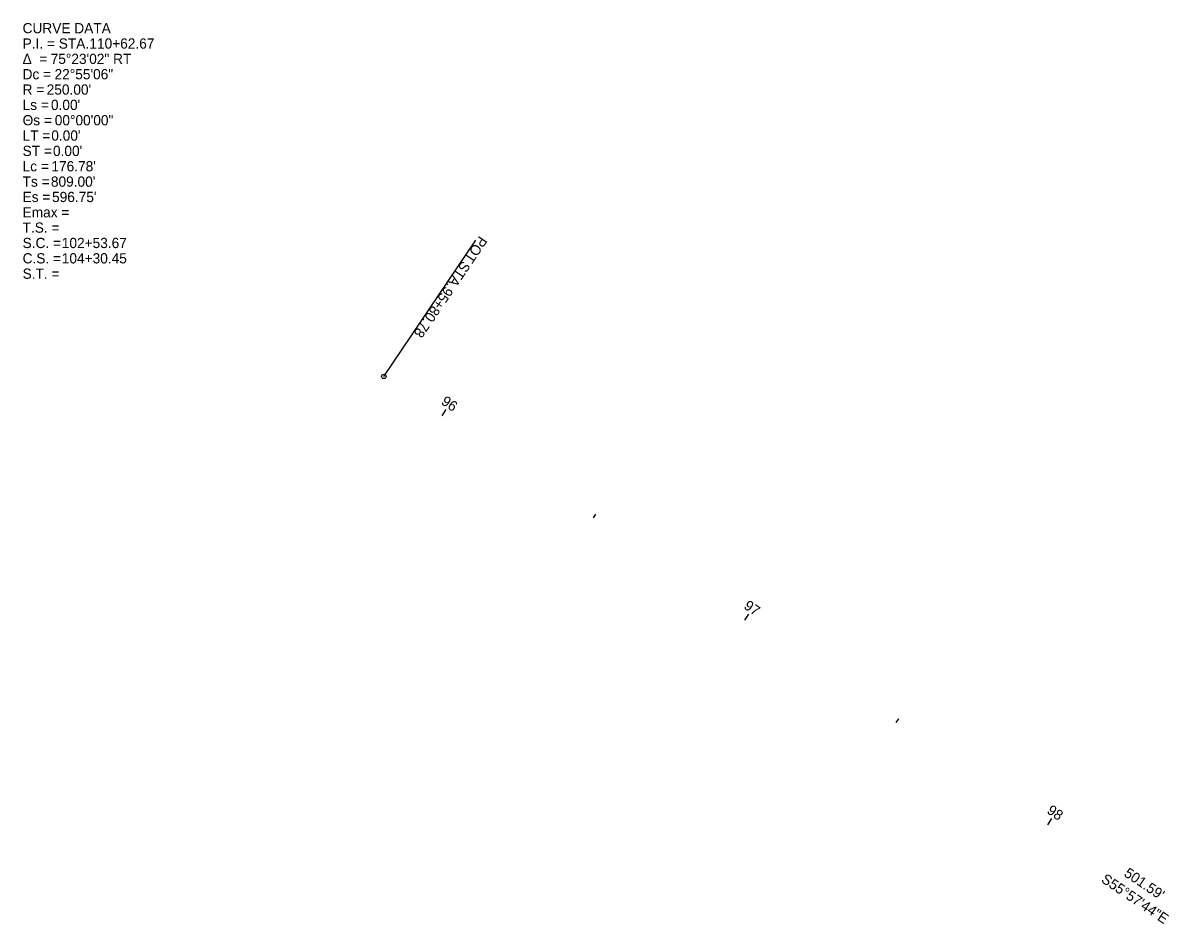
# Model space of a CAD drawing. Extents: x 1600023 to 1602131, y 285824 to 287284.
# Drawn here: x 1600258.1 to 1600571.8, y 287037.4 to 287284.1 of the extents above; entities that cross this region are included whole.
import ezdxf

# ---------------------------------------------------------------- set-up
doc = ezdxf.new("R2010")
doc.units = 0
for name, color, linetype in [('GE_P_Alignment_100_Bearings', 7, 'Continuous'), ('GE_P_Alignment_100_Cardinal_Points', 7, 'Continuous'), ('GE_P_Alignment_100_Curve_Data', 7, 'Continuous'), ('GE_P_Alignment_100_Distances', 7, 'Continuous'), ('GE_P_Alignment_100_Stations', 7, 'Continuous')]:
    doc.layers.add(name, color=color, linetype=linetype)

msp = doc.modelspace()

# ---------------------------------------------------------------- linework, layer by layer
at = {"layer": 'GE_P_Alignment_100_Cardinal_Points'}
msp.add_line((1600356.88, 287187.32), (1600382.06, 287224.61), dxfattribs=at)
msp.add_circle((1600356.88, 287187.32), 0.6, dxfattribs=at)
at = {"layer": 'GE_P_Alignment_100_Stations'}
for p, q in [((1600372.8, 287176.56), (1600373.92, 287178.22)), ((1600414.24, 287148.57), (1600414.91, 287149.57)), ((1600455.67, 287120.59), (1600456.79, 287122.24)), ((1600497.1, 287092.6), (1600497.78, 287093.59)), ((1600538.54, 287064.61), (1600539.66, 287066.27))]:
    msp.add_line(p, q, dxfattribs=at)

# ---------------------------------------------------------------- texts
at = {"layer": 'GE_P_Alignment_100_Bearings'}
msp.add_text('S55°57\'44"E', height=2.8, rotation=325.9623, dxfattribs=at).set_placement((1600552.95, 287049.08))
at = {"layer": 'GE_P_Alignment_100_Cardinal_Points'}
for s, p in [('POT', (1600383.03, 287225.97)), (' STA. ', (1600379, 287220)), ('95+80.78', (1600373.71, 287212.17))]:
    msp.add_text(s, height=2.8, rotation=235.9623, dxfattribs=at).set_placement(p)
at = {"layer": 'GE_P_Alignment_100_Curve_Data'}
for s, p in [('CURVE DATA', (1600258.03, 287281.25)), ('P.I. = STA. ', (1600258.03, 287277.05)), ('110+62.67', (1600276.3, 287277.05)), ('Δ  = ', (1600258.03, 287272.85)), ('75°23\'02" RT', (1600265.71, 287272.85)), ('Dc = ', (1600258.03, 287268.65)), ('22°55\'06"', (1600266.77, 287268.65)), ('R = ', (1600258.03, 287264.45)), ("250.00'", (1600264.62, 287264.45)), ('Ls = ', (1600258.03, 287260.25)), ("0.00'", (1600265.79, 287260.25)), ('Θs = ', (1600258.03, 287256.05)), ('00°00\'00"', (1600266.83, 287256.05)), ('LT = ', (1600258.03, 287251.85)), ("0.00'", (1600265.88, 287251.85)), ('ST = ', (1600258.03, 287247.65)), ("0.00'", (1600266.34, 287247.65)), ('Lc = ', (1600258.03, 287243.45)), ("176.78'", (1600265.91, 287243.45)), ('Ts = ', (1600258.03, 287239.25)), ("809.00'", (1600265.77, 287239.25)), ('Es = ', (1600258.03, 287235.05)), ("596.75'", (1600266.09, 287235.05)), ('Emax = ', (1600258.03, 287230.85)), ('T.S. = ', (1600258.03, 287226.65)), ('S.C. = ', (1600258.03, 287222.45)), ('102+53.67', (1600268.75, 287222.45)), ('C.S. = ', (1600258.03, 287218.25)), ('104+30.45', (1600268.75, 287218.25)), ('S.T. = ', (1600258.03, 287214.05))]:
    msp.add_text(s, height=2.8, dxfattribs=at).set_placement(p)
at = {"layer": 'GE_P_Alignment_100_Distances'}
msp.add_text("501.59'", height=2.8, rotation=325.9623, dxfattribs=at).set_placement((1600559.19, 287050.71))
at = {"layer": 'GE_P_Alignment_100_Stations'}
for s, p in [('96', (1600372.35, 287179.89)), ('97', (1600455.16, 287123.94)), ('98', (1600538.1, 287067.93))]:
    msp.add_text(s, height=2.8, rotation=325.9623, dxfattribs=at).set_placement(p)

doc.saveas('drawing.dxf')
